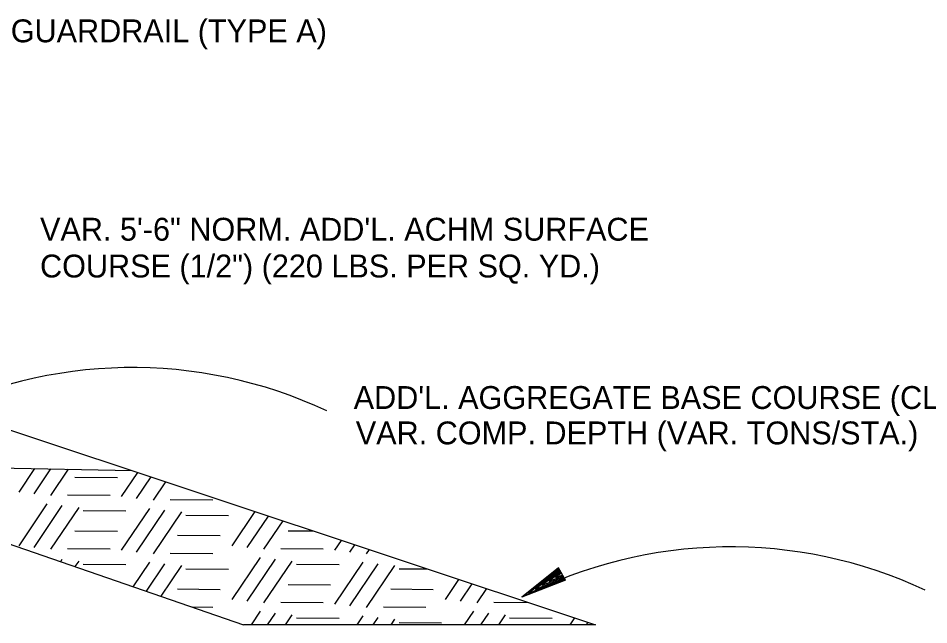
# Model space of a CAD drawing. Extents: x 1929624 to 1936506, y 596315 to 605721.
# Drawn here: x 1934166.9 to 1934408.7, y 604077.3 to 604238.3 of the extents above; entities that cross this region are included whole.
import ezdxf

# ---------------------------------------------------------------- set-up
doc = ezdxf.new("R2010")
doc.units = 0
doc.layers.add('Default', color=7, linetype='Continuous')
doc.layers.add('R_Border', color=7, linetype='Continuous')

msp = doc.modelspace()

# ---------------------------------------------------------------- linework, layer by layer
at = {"layer": 'Default'}
for p, q in [((1934139.58, 604137.31), (1934320.2, 604077.27)), ((1933803.65, 604126.05), (1934197.03, 604118.22)), ((1934102.69, 604120.1), (1934226.74, 604077.27)), ((1934310.33, 604092.35), (1934300.59, 604084.58)), ((1934310.5, 604092.06), (1934302.38, 604085.59)), ((1934310.65, 604091.79), (1934304.2, 604086.67)), ((1934310.8, 604091.54), (1934305.97, 604087.7)), ((1934310.94, 604091.24), (1934307.77, 604088.73)), ((1934311.12, 604090.97), (1934309.59, 604089.77)), ((1934312.2, 604089.13), (1934310.33, 604092.35)), ((1934312.2, 604089.13), (1934300.59, 604084.58)), ((1934312.03, 604089.4), (1934302.38, 604085.59)), ((1934311.85, 604089.67), (1934304.2, 604086.67)), ((1934311.71, 604089.92), (1934305.97, 604087.7)), ((1934311.56, 604090.19), (1934307.77, 604088.73)), ((1934311.41, 604090.48), (1934309.59, 604089.77)), ((1934320.2, 604077.27), (1934226.74, 604077.27)), ((1934319.68, 604077.27), (1934319.81, 604077.4)), ((1934320.11, 604077.3), (1934320.14, 604077.27))]:
    msp.add_line(p, q, dxfattribs=at)
for centre in [(1934197.2, 604023.84), (1934356.1, 603976.24)]:
    msp.add_arc(centre, 121.72, 64.8876, 117.1378, dxfattribs=at)
at = {"layer": 'R_Border'}
for p, q in [((1934167.09, 604112.51), (1934171.29, 604118.73)), ((1934171.08, 604112.05), (1934175.53, 604118.65)), ((1934175.53, 604111.59), (1934180.23, 604118.56)), ((1934194.35, 604111.31), (1934198.64, 604117.68)), ((1934181.92, 604116.5), (1934193.23, 604116.41)), ((1934198.33, 604110.84), (1934202.16, 604116.51)), ((1934202.78, 604110.38), (1934206.05, 604115.22)), ((1934179.98, 604111.77), (1934191.29, 604111.68)), ((1934207.23, 604110.57), (1934218.54, 604110.47)), ((1934167.09, 604098.25), (1934174.6, 604109.38)), ((1934171.08, 604097.79), (1934178.59, 604108.92)), ((1934175.53, 604097.32), (1934183.04, 604108.45)), ((1934194.35, 604097.05), (1934201.86, 604108.18)), ((1934198.33, 604096.58), (1934205.84, 604107.71)), ((1934184.15, 604107.62), (1934195.46, 604107.53)), ((1934202.78, 604096.12), (1934210.29, 604107.25)), ((1934211.4, 604106.41), (1934222.71, 604106.32)), ((1934223.71, 604098.25), (1934229.83, 604107.31)), ((1934227.7, 604097.79), (1934233.34, 604106.15)), ((1934232.15, 604097.32), (1934237.23, 604104.85)), ((1934181.92, 604102.24), (1934193.23, 604102.15)), ((1934209.18, 604101.03), (1934220.49, 604100.94)), ((1934238.54, 604102.24), (1934245.25, 604102.19)), ((1934250.97, 604097.05), (1934252.75, 604099.69)), ((1934254.95, 604096.58), (1934256.26, 604098.52)), ((1934179.98, 604097.51), (1934191.29, 604097.42)), ((1934207.23, 604096.3), (1934218.54, 604096.21)), ((1934236.6, 604097.51), (1934247.91, 604097.42)), ((1934259.4, 604096.12), (1934260.15, 604097.23)), ((1934178.17, 604094.04), (1934178.59, 604094.66)), ((1934182.03, 604092.7), (1934183.04, 604094.19)), ((1934184.15, 604093.36), (1934195.46, 604093.26)), ((1934197.45, 604087.38), (1934201.86, 604093.91)), ((1934200.94, 604086.18), (1934205.84, 604093.45)), ((1934223.71, 604083.99), (1934231.22, 604095.12)), ((1934227.7, 604083.53), (1934235.21, 604094.66)), ((1934232.15, 604083.06), (1934239.66, 604094.19)), ((1934240.77, 604093.36), (1934252.08, 604093.26)), ((1934250.97, 604082.78), (1934258.48, 604093.91)), ((1934254.95, 604082.32), (1934262.46, 604093.45)), ((1934204.8, 604084.85), (1934210.29, 604092.99)), ((1934211.4, 604092.15), (1934222.71, 604092.06)), ((1934259.4, 604081.86), (1934266.91, 604092.99)), ((1934268.02, 604092.15), (1934275.62, 604092.09)), ((1934280.33, 604083.99), (1934283.93, 604089.33)), ((1934209.18, 604086.77), (1934220.49, 604086.68)), ((1934238.54, 604087.98), (1934249.85, 604087.89)), ((1934265.8, 604086.77), (1934277.11, 604086.68)), ((1934284.32, 604083.53), (1934287.45, 604088.16)), ((1934288.77, 604083.06), (1934291.33, 604086.87)), ((1934213.05, 604082), (1934218.54, 604081.95)), ((1934236.6, 604083.25), (1934247.91, 604083.16)), ((1934263.85, 604082.04), (1934275.16, 604081.95)), ((1934293.22, 604083.25), (1934302.44, 604083.17)), ((1934228.8, 604077.27), (1934231.22, 604080.86)), ((1934233.1, 604077.27), (1934235.21, 604080.39)), ((1934237.86, 604077.27), (1934239.66, 604079.93)), ((1934240.77, 604079.09), (1934252.08, 604079)), ((1934256.87, 604077.27), (1934258.48, 604079.65)), ((1934261.17, 604077.27), (1934262.46, 604079.19)), ((1934265.93, 604077.27), (1934266.91, 604078.72)), ((1934285.42, 604077.27), (1934287.84, 604080.86)), ((1934289.72, 604077.27), (1934291.83, 604080.39)), ((1934294.48, 604077.27), (1934296.28, 604079.93)), ((1934297.39, 604079.09), (1934308.7, 604079)), ((1934313.49, 604077.27), (1934314.72, 604079.09)), ((1934268.02, 604077.89), (1934279.33, 604077.8)), ((1934317.79, 604077.27), (1934318.23, 604077.92))]:
    msp.add_line(p, q, dxfattribs=at)

# ---------------------------------------------------------------- texts
at = {"layer": 'Default'}
for s, p in [('GUARDRAIL (TYPE A)', (1934164.9, 604231.92)), ('VAR. 5\'-6" NORM. ADD\'L. ACHM SURFACE ', (1934172.68, 604179.25)), ('COURSE (1/2") (220 LBS. PER SQ. YD.)', (1934172.68, 604169.48)), ("ADD'L. AGGREGATE BASE COURSE (CLASS 7)", (1934255.98, 604134.57)), ('VAR. COMP. DEPTH (VAR. TONS/STA.)', (1934256.54, 604125.17))]:
    msp.add_text(s, height=6.075, rotation=360, dxfattribs=at).set_placement(p)

doc.saveas('drawing.dxf')
